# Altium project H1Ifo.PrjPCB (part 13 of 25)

## Sheet IfoSqz1.SchDoc: D1800185
size C; Engineer: Daniel Sigg; DocumentNumber: 4; Revision: 4; SheetNumber: 4; SheetTotal: 10
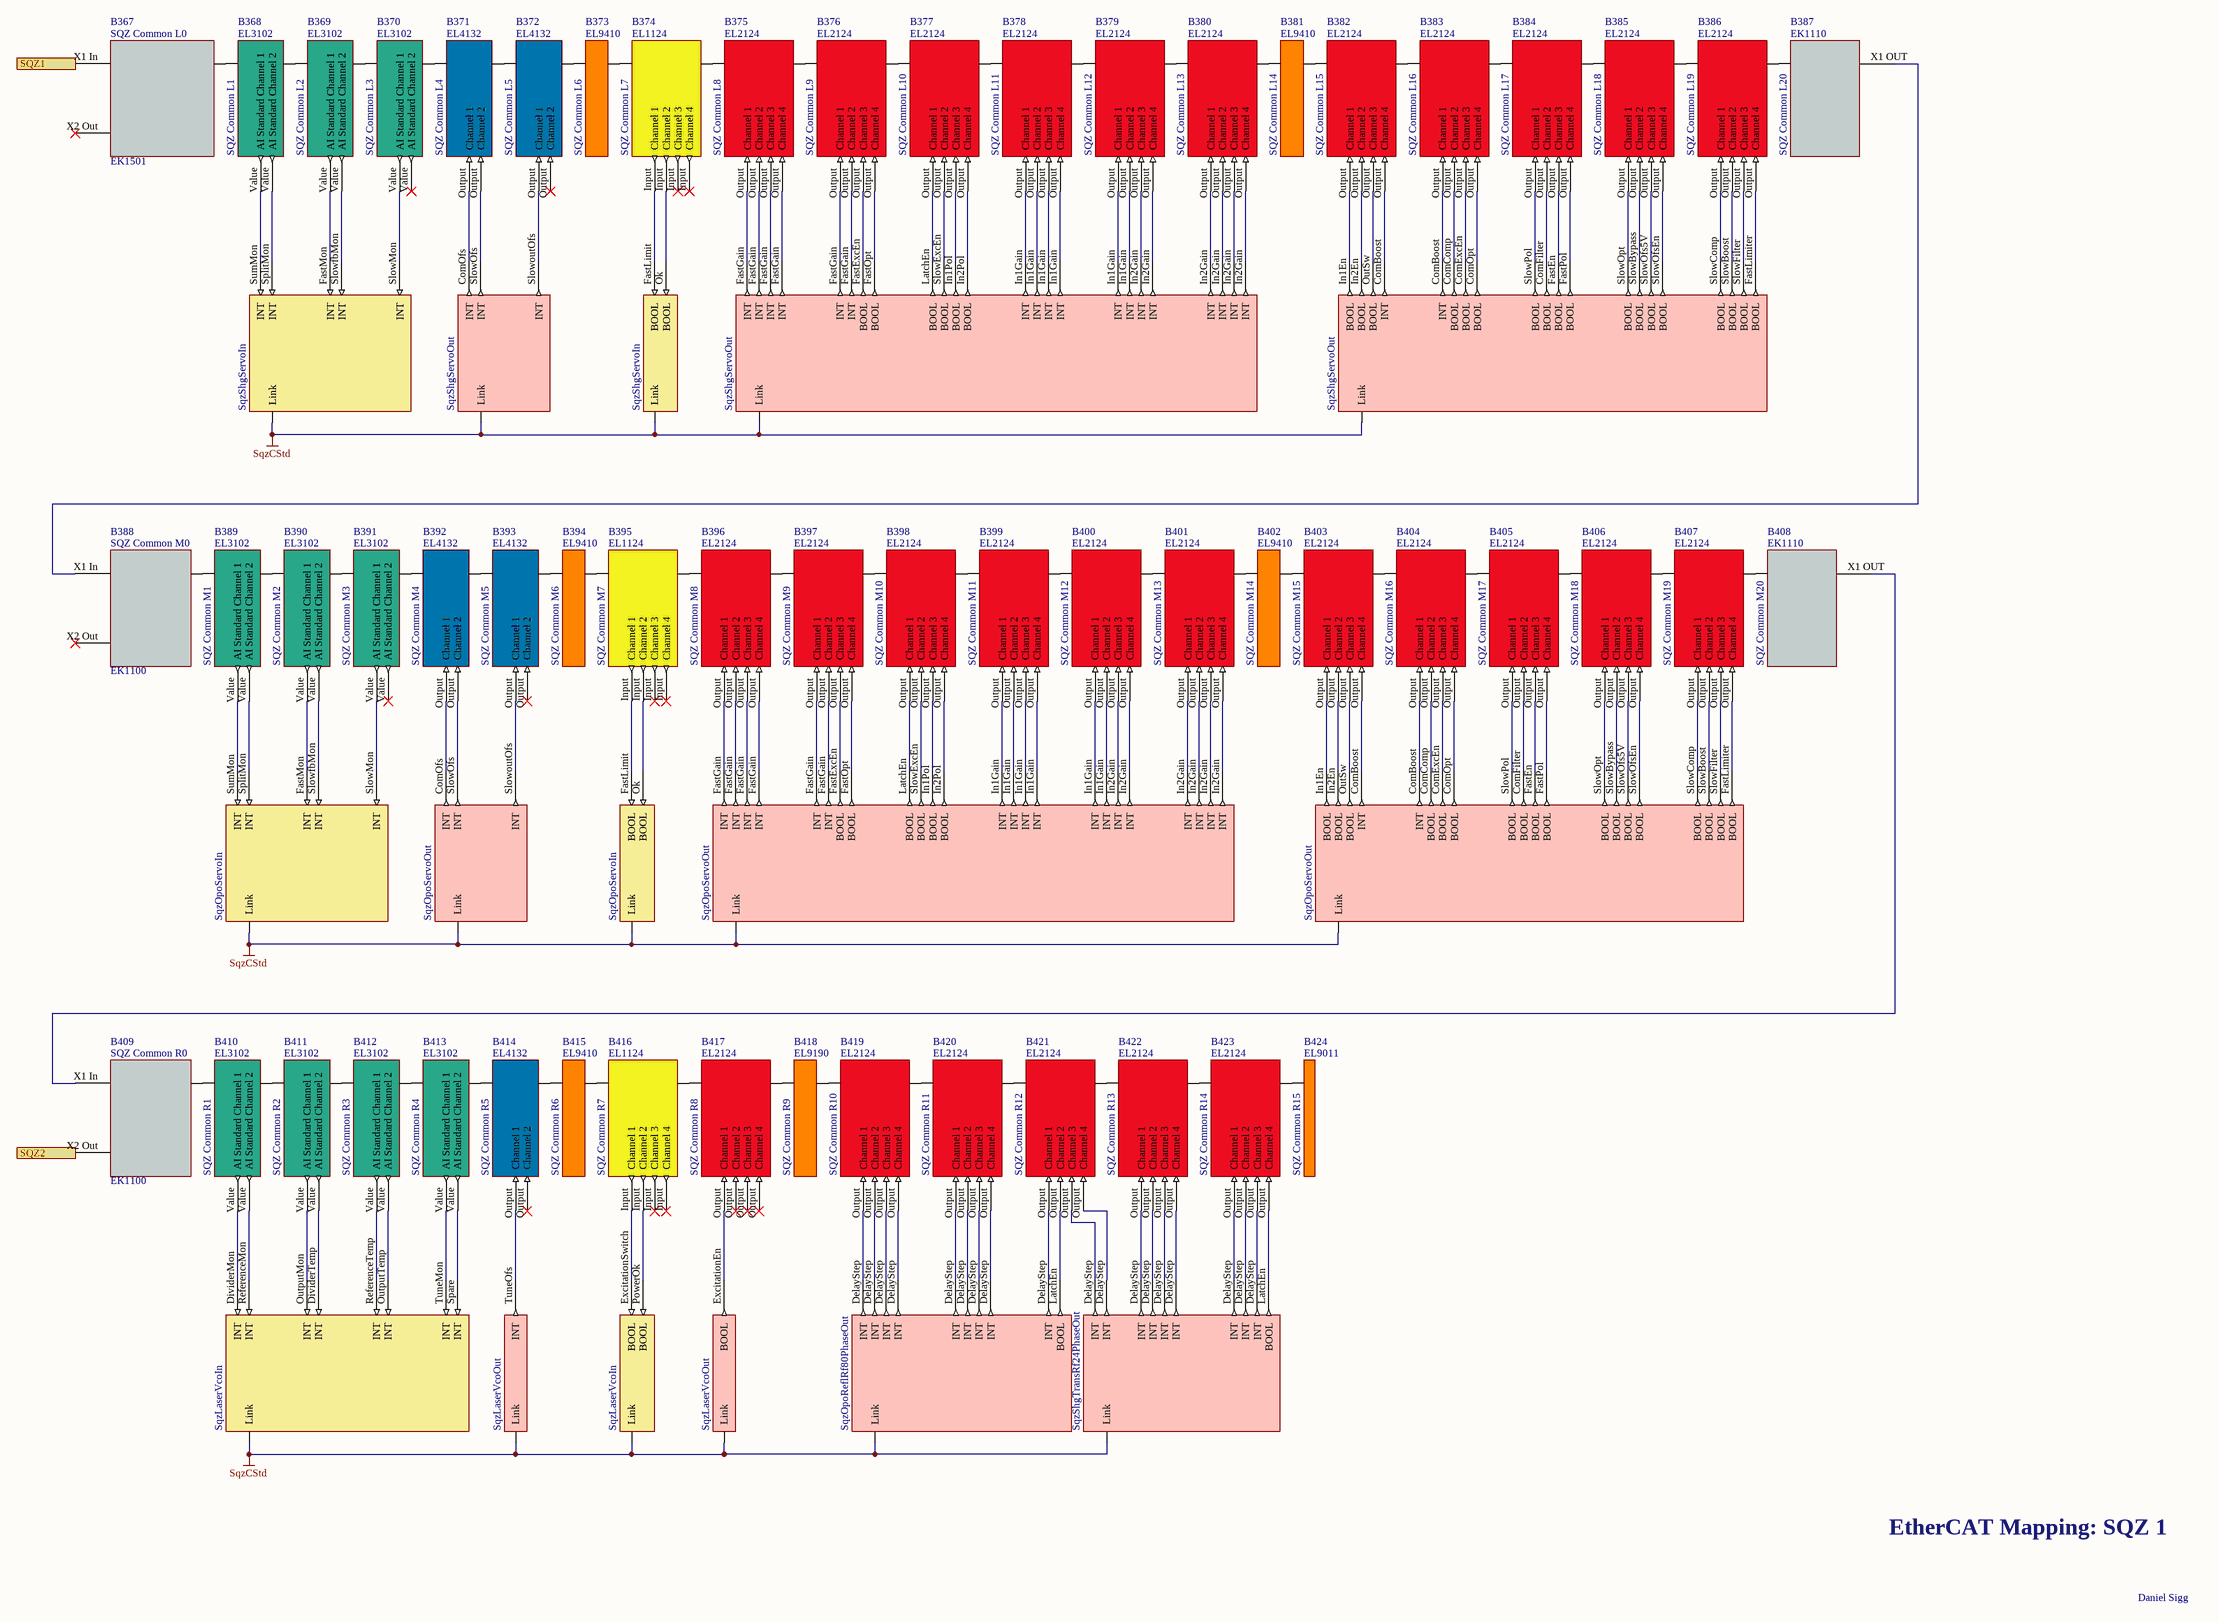
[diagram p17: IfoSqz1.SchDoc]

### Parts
B367  SQZ Common L0  Part Number: EK1501  (mechanical)
B368  SQZ Common L1  Part Number: EL3102  (mechanical)
B369  SQZ Common L2  Part Number: EL3102  (mechanical)
B370  SQZ Common L3  Part Number: EL3102  (mechanical)
B371  SQZ Common L4  Part Number: EL4132  (mechanical)
B372  SQZ Common L5  Part Number: EL4132  (mechanical)
B373  SQZ Common L6  Part Number: EL9410  (mechanical)
B374  SQZ Common L7  Part Number: EL1124  (mechanical)
B375  SQZ Common L8  Part Number: EL2124  (mechanical)
B376  SQZ Common L9  Part Number: EL2124  (mechanical)
B377  SQZ Common L10  Part Number: EL2124  (mechanical)
B378  SQZ Common L11  Part Number: EL2124  (mechanical)
B379  SQZ Common L12  Part Number: EL2124  (mechanical)
B380  SQZ Common L13  Part Number: EL2124  (mechanical)
B381  SQZ Common L14  Part Number: EL9410  (mechanical)
B382  SQZ Common L15  Part Number: EL2124  (mechanical)
B383  SQZ Common L16  Part Number: EL2124  (mechanical)
B384  SQZ Common L17  Part Number: EL2124  (mechanical)
B385  SQZ Common L18  Part Number: EL2124  (mechanical)
B386  SQZ Common L19  Part Number: EL2124  (mechanical)
B387  SQZ Common L20  Part Number: EK1110  (mechanical)
B388  SQZ Common M0  Part Number: EK1100  (mechanical)
B389  SQZ Common M1  Part Number: EL3102  (mechanical)
B390  SQZ Common M2  Part Number: EL3102  (mechanical)
B391  SQZ Common M3  Part Number: EL3102  (mechanical)
B392  SQZ Common M4  Part Number: EL4132  (mechanical)
B393  SQZ Common M5  Part Number: EL4132  (mechanical)
B394  SQZ Common M6  Part Number: EL9410  (mechanical)
B395  SQZ Common M7  Part Number: EL1124  (mechanical)
B396  SQZ Common M8  Part Number: EL2124  (mechanical)
B397  SQZ Common M9  Part Number: EL2124  (mechanical)
B398  SQZ Common M10  Part Number: EL2124  (mechanical)
B399  SQZ Common M11  Part Number: EL2124  (mechanical)
B400  SQZ Common M12  Part Number: EL2124  (mechanical)
B401  SQZ Common M13  Part Number: EL2124  (mechanical)
B402  SQZ Common M14  Part Number: EL9410  (mechanical)
B403  SQZ Common M15  Part Number: EL2124  (mechanical)
B404  SQZ Common M16  Part Number: EL2124  (mechanical)
B405  SQZ Common M17  Part Number: EL2124  (mechanical)
B406  SQZ Common M18  Part Number: EL2124  (mechanical)
B407  SQZ Common M19  Part Number: EL2124  (mechanical)
B408  SQZ Common M20  Part Number: EK1110  (mechanical)
B409  SQZ Common R0  Part Number: EK1100  (mechanical)
B410  SQZ Common R1  Part Number: EL3102  (mechanical)
B411  SQZ Common R2  Part Number: EL3102  (mechanical)
B412  SQZ Common R3  Part Number: EL3102  (mechanical)
B413  SQZ Common R4  Part Number: EL3102  (mechanical)
B414  SQZ Common R5  Part Number: EL4132  (mechanical)
B415  SQZ Common R6  Part Number: EL9410  (mechanical)
B416  SQZ Common R7  Part Number: EL1124  (mechanical)
B417  SQZ Common R8  Part Number: EL2124  (mechanical)
B418  SQZ Common R9  Part Number: EL9190  (mechanical)
B419  SQZ Common R10  Part Number: EL2124  (mechanical)
B420  SQZ Common R11  Part Number: EL2124  (mechanical)
B421  SQZ Common R12  Part Number: EL2124  (mechanical)
B422  SQZ Common R13  Part Number: EL2124  (mechanical)
B423  SQZ Common R14  Part Number: EL2124  (mechanical)
B424  SQZ Common R15  Part Number: EL9011  (mechanical)
V258  SqzShgServoIn  (parts A,B of 2)  (no BOM)
V259  SqzShgServoOut  (parts A,B,C of 3)  (no BOM)
V262  SqzOpoServoIn  (parts A,B of 2)  (no BOM)
V263  SqzOpoServoOut  (parts A,B,C of 3)  (no BOM)
V328  SqzLaserVcoIn  (parts A,B of 2)  (no BOM)
V445  SqzLaserVcoOut  (parts A,B of 2)  (no BOM)
V446  SqzOpoReflRf80PhaseOut  (no BOM)
V447  SqzShgTransRf24PhaseOut  (no BOM)

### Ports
SQZ1, SQZ2

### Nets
SqzCStd: V258.1(Link) V258.?1(Link) V259.1(Link) V259.2(Link) V259.?1(Link) V262.1(Link) V262.?1(Link) V263.1(Link) V263.2(Link) V263.?1(Link) V328.0(Link) V328.1(Link) V445.0(Link) V445.1(Link) V446.?1(Link) V447.?1(Link)
NetB367_Ebus: B367.Ebus(B) B368.Ebus(A)
NetB367_X1 In: B367.X1_In(A) ; port SQZ1
NetB368_Ebus: B368.Ebus(B) B369.Ebus(A)
NetB368_Value: B368.Value(AI_Standard_Channel_1) V258.SumMon(INT)
NetB368_Value: B368.Value(AI_Standard_Channel_2) V258.SplitMon(INT)  [a separate net that carries the same name]
NetB369_Ebus: B369.Ebus(B) B370.Ebus(A)
NetB369_Value: B369.Value(AI_Standard_Channel_1) V258.FastMon(INT)
NetB369_Value: B369.Value(AI_Standard_Channel_2) V258.SlowfbMon(INT)  [a separate net that carries the same name]
NetB370_Ebus: B370.Ebus(B) B371.Ebus(A)
NetB370_Value: B370.Value(AI_Standard_Channel_1) V258.SlowMon(INT)
NetB371_Ebus: B371.Ebus(B) B372.Ebus(A)
NetB371_Output: B371.Output(Channel_1) V259.ComOfs(INT)
NetB371_Output: B371.Output(Channel_2) V259.SlowOfs(INT)  [a separate net that carries the same name]
NetB372_Ebus: B372.Ebus(B) B373.Ebus(A)
NetB372_Output: B372.Output(Channel_1) V259.SlowoutOfs(INT)
NetB373_Ebus: B373.Ebus(B) B374.Ebus(A)
NetB374_Ebus: B374.Ebus(B) B375.Ebus(A)
NetB374_Input: B374.Input(Channel_1) V258.FastLimit(BOOL)
NetB374_Input: B374.Input(Channel_2) V258.Ok(BOOL)  [a separate net that carries the same name]
NetB375_Ebus: B375.Ebus(B) B376.Ebus(A)
NetB375_Output: B375.Output(Channel_1) V259.FastGain(INT)
NetB375_Output: B375.Output(Channel_2) V259.FastGain(INT)  [a separate net that carries the same name]
NetB375_Output: B375.Output(Channel_3) V259.FastGain(INT)  [a separate net that carries the same name]
NetB375_Output: B375.Output(Channel_4) V259.FastGain(INT)  [a separate net that carries the same name]
NetB376_Ebus: B376.Ebus(B) B377.Ebus(A)
NetB376_Output: B376.Output(Channel_1) V259.FastGain(INT)
NetB376_Output: B376.Output(Channel_2) V259.FastGain(INT)  [a separate net that carries the same name]
NetB376_Output: B376.Output(Channel_3) V259.FastExcEn(BOOL)  [a separate net that carries the same name]
NetB376_Output: B376.Output(Channel_4) V259.FastOpt(BOOL)  [a separate net that carries the same name]
NetB377_Ebus: B377.Ebus(B) B378.Ebus(A)
NetB377_Output: B377.Output(Channel_1) V259.LatchEn(BOOL)
NetB377_Output: B377.Output(Channel_2) V259.SlowExcEn(BOOL)  [a separate net that carries the same name]
NetB377_Output: B377.Output(Channel_3) V259.In1Pol(BOOL)  [a separate net that carries the same name]
NetB377_Output: B377.Output(Channel_4) V259.In2Pol(BOOL)  [a separate net that carries the same name]
NetB378_Ebus: B378.Ebus(B) B379.Ebus(A)
NetB378_Output: B378.Output(Channel_1) V259.In1Gain(INT)
NetB378_Output: B378.Output(Channel_2) V259.In1Gain(INT)  [a separate net that carries the same name]
NetB378_Output: B378.Output(Channel_3) V259.In1Gain(INT)  [a separate net that carries the same name]
NetB378_Output: B378.Output(Channel_4) V259.In1Gain(INT)  [a separate net that carries the same name]
NetB379_Ebus: B379.Ebus(B) B380.Ebus(A)
NetB379_Output: B379.Output(Channel_1) V259.In1Gain(INT)
NetB379_Output: B379.Output(Channel_2) V259.In1Gain(INT)  [a separate net that carries the same name]
NetB379_Output: B379.Output(Channel_3) V259.In2Gain(INT)  [a separate net that carries the same name]
NetB379_Output: B379.Output(Channel_4) V259.In2Gain(INT)  [a separate net that carries the same name]
NetB380_Ebus: B380.Ebus(B) B381.Ebus(A)
NetB380_Output: B380.Output(Channel_1) V259.In2Gain(INT)
NetB380_Output: B380.Output(Channel_2) V259.In2Gain(INT)  [a separate net that carries the same name]
NetB380_Output: B380.Output(Channel_3) V259.In2Gain(INT)  [a separate net that carries the same name]
NetB380_Output: B380.Output(Channel_4) V259.In2Gain(INT)  [a separate net that carries the same name]
NetB381_Ebus: B381.Ebus(B) B382.Ebus(A)
NetB382_Ebus: B382.Ebus(B) B383.Ebus(A)
NetB382_Output: B382.Output(Channel_1) V259.In1En(BOOL)
NetB382_Output: B382.Output(Channel_2) V259.In2En(BOOL)  [a separate net that carries the same name]
NetB382_Output: B382.Output(Channel_3) V259.OutSw(BOOL)  [a separate net that carries the same name]
NetB382_Output: B382.Output(Channel_4) V259.ComBoost(INT)  [a separate net that carries the same name]
NetB383_Ebus: B383.Ebus(B) B384.Ebus(A)
NetB383_Output: B383.Output(Channel_1) V259.ComBoost(INT)
NetB383_Output: B383.Output(Channel_2) V259.ComComp(BOOL)  [a separate net that carries the same name]
NetB383_Output: B383.Output(Channel_3) V259.ComExcEn(BOOL)  [a separate net that carries the same name]
NetB383_Output: B383.Output(Channel_4) V259.ComOpt(BOOL)  [a separate net that carries the same name]
NetB384_Ebus: B384.Ebus(B) B385.Ebus(A)
NetB384_Output: B384.Output(Channel_1) V259.SlowPol(BOOL)
NetB384_Output: B384.Output(Channel_2) V259.ComFilter(BOOL)  [a separate net that carries the same name]
NetB384_Output: B384.Output(Channel_3) V259.FastEn(BOOL)  [a separate net that carries the same name]
NetB384_Output: B384.Output(Channel_4) V259.FastPol(BOOL)  [a separate net that carries the same name]
NetB385_Ebus: B385.Ebus(B) B386.Ebus(A)
NetB385_Output: B385.Output(Channel_1) V259.SlowOpt(BOOL)
NetB385_Output: B385.Output(Channel_2) V259.SlowBypass(BOOL)  [a separate net that carries the same name]
NetB385_Output: B385.Output(Channel_3) V259.SlowOfs5V(BOOL)  [a separate net that carries the same name]
NetB385_Output: B385.Output(Channel_4) V259.SlowOfsEn(BOOL)  [a separate net that carries the same name]
NetB386_Ebus: B386.Ebus(B) B387.Ebus(A)
NetB386_Output: B386.Output(Channel_1) V259.SlowComp(BOOL)
NetB386_Output: B386.Output(Channel_2) V259.SlowBoost(BOOL)  [a separate net that carries the same name]
NetB386_Output: B386.Output(Channel_3) V259.SlowFilter(BOOL)  [a separate net that carries the same name]
NetB386_Output: B386.Output(Channel_4) V259.FastLimiter(BOOL)  [a separate net that carries the same name]
NetB387_X1 OUT: B387.X1_OUT(B) B388.X1_In(A)
NetB388_Ebus: B388.Ebus(B) B389.Ebus(A)
NetB389_Ebus: B389.Ebus(B) B390.Ebus(A)
NetB389_Value: B389.Value(AI_Standard_Channel_1) V262.SumMon(INT)
NetB389_Value: B389.Value(AI_Standard_Channel_2) V262.SplitMon(INT)  [a separate net that carries the same name]
NetB390_Ebus: B390.Ebus(B) B391.Ebus(A)
NetB390_Value: B390.Value(AI_Standard_Channel_1) V262.FastMon(INT)
NetB390_Value: B390.Value(AI_Standard_Channel_2) V262.SlowfbMon(INT)  [a separate net that carries the same name]
NetB391_Ebus: B391.Ebus(B) B392.Ebus(A)
NetB391_Value: B391.Value(AI_Standard_Channel_1) V262.SlowMon(INT)
NetB392_Ebus: B392.Ebus(B) B393.Ebus(A)
NetB392_Output: B392.Output(Channel_1) V263.ComOfs(INT)
NetB392_Output: B392.Output(Channel_2) V263.SlowOfs(INT)  [a separate net that carries the same name]
NetB393_Ebus: B393.Ebus(B) B394.Ebus(A)
NetB393_Output: B393.Output(Channel_1) V263.SlowoutOfs(INT)
NetB394_Ebus: B394.Ebus(B) B395.Ebus(A)
NetB395_Ebus: B395.Ebus(B) B396.Ebus(A)
NetB395_Input: B395.Input(Channel_1) V262.FastLimit(BOOL)
NetB395_Input: B395.Input(Channel_2) V262.Ok(BOOL)  [a separate net that carries the same name]
NetB396_Ebus: B396.Ebus(B) B397.Ebus(A)
NetB396_Output: B396.Output(Channel_1) V263.FastGain(INT)
NetB396_Output: B396.Output(Channel_2) V263.FastGain(INT)  [a separate net that carries the same name]
NetB396_Output: B396.Output(Channel_3) V263.FastGain(INT)  [a separate net that carries the same name]
NetB396_Output: B396.Output(Channel_4) V263.FastGain(INT)  [a separate net that carries the same name]
NetB397_Ebus: B397.Ebus(B) B398.Ebus(A)
NetB397_Output: B397.Output(Channel_1) V263.FastGain(INT)
NetB397_Output: B397.Output(Channel_2) V263.FastGain(INT)  [a separate net that carries the same name]
NetB397_Output: B397.Output(Channel_3) V263.FastExcEn(BOOL)  [a separate net that carries the same name]
NetB397_Output: B397.Output(Channel_4) V263.FastOpt(BOOL)  [a separate net that carries the same name]
NetB398_Ebus: B398.Ebus(B) B399.Ebus(A)
NetB398_Output: B398.Output(Channel_1) V263.LatchEn(BOOL)
NetB398_Output: B398.Output(Channel_2) V263.SlowExcEn(BOOL)  [a separate net that carries the same name]
NetB398_Output: B398.Output(Channel_3) V263.In1Pol(BOOL)  [a separate net that carries the same name]
NetB398_Output: B398.Output(Channel_4) V263.In2Pol(BOOL)  [a separate net that carries the same name]
NetB399_Ebus: B399.Ebus(B) B400.Ebus(A)
NetB399_Output: B399.Output(Channel_1) V263.In1Gain(INT)
NetB399_Output: B399.Output(Channel_2) V263.In1Gain(INT)  [a separate net that carries the same name]
NetB399_Output: B399.Output(Channel_3) V263.In1Gain(INT)  [a separate net that carries the same name]
NetB399_Output: B399.Output(Channel_4) V263.In1Gain(INT)  [a separate net that carries the same name]
NetB400_Ebus: B400.Ebus(B) B401.Ebus(A)
NetB400_Output: B400.Output(Channel_1) V263.In1Gain(INT)
NetB400_Output: B400.Output(Channel_2) V263.In1Gain(INT)  [a separate net that carries the same name]
NetB400_Output: B400.Output(Channel_3) V263.In2Gain(INT)  [a separate net that carries the same name]
NetB400_Output: B400.Output(Channel_4) V263.In2Gain(INT)  [a separate net that carries the same name]
NetB401_Ebus: B401.Ebus(B) B402.Ebus(A)
NetB401_Output: B401.Output(Channel_1) V263.In2Gain(INT)
NetB401_Output: B401.Output(Channel_2) V263.In2Gain(INT)  [a separate net that carries the same name]
NetB401_Output: B401.Output(Channel_3) V263.In2Gain(INT)  [a separate net that carries the same name]
NetB401_Output: B401.Output(Channel_4) V263.In2Gain(INT)  [a separate net that carries the same name]
NetB402_Ebus: B402.Ebus(B) B403.Ebus(A)
NetB403_Ebus: B403.Ebus(B) B404.Ebus(A)
NetB403_Output: B403.Output(Channel_1) V263.In1En(BOOL)
NetB403_Output: B403.Output(Channel_2) V263.In2En(BOOL)  [a separate net that carries the same name]
NetB403_Output: B403.Output(Channel_3) V263.OutSw(BOOL)  [a separate net that carries the same name]
NetB403_Output: B403.Output(Channel_4) V263.ComBoost(INT)  [a separate net that carries the same name]
NetB404_Ebus: B404.Ebus(B) B405.Ebus(A)
NetB404_Output: B404.Output(Channel_1) V263.ComBoost(INT)
NetB404_Output: B404.Output(Channel_2) V263.ComComp(BOOL)  [a separate net that carries the same name]
NetB404_Output: B404.Output(Channel_3) V263.ComExcEn(BOOL)  [a separate net that carries the same name]
NetB404_Output: B404.Output(Channel_4) V263.ComOpt(BOOL)  [a separate net that carries the same name]
NetB405_Ebus: B405.Ebus(B) B406.Ebus(A)
NetB405_Output: B405.Output(Channel_1) V263.SlowPol(BOOL)
NetB405_Output: B405.Output(Channel_2) V263.ComFilter(BOOL)  [a separate net that carries the same name]
NetB405_Output: B405.Output(Channel_3) V263.FastEn(BOOL)  [a separate net that carries the same name]
NetB405_Output: B405.Output(Channel_4) V263.FastPol(BOOL)  [a separate net that carries the same name]
NetB406_Ebus: B406.Ebus(B) B407.Ebus(A)
NetB406_Output: B406.Output(Channel_1) V263.SlowOpt(BOOL)
NetB406_Output: B406.Output(Channel_2) V263.SlowBypass(BOOL)  [a separate net that carries the same name]
NetB406_Output: B406.Output(Channel_3) V263.SlowOfs5V(BOOL)  [a separate net that carries the same name]
NetB406_Output: B406.Output(Channel_4) V263.SlowOfsEn(BOOL)  [a separate net that carries the same name]
NetB407_Ebus: B407.Ebus(B) B408.Ebus(A)
NetB407_Output: B407.Output(Channel_1) V263.SlowComp(BOOL)
NetB407_Output: B407.Output(Channel_2) V263.SlowBoost(BOOL)  [a separate net that carries the same name]
NetB407_Output: B407.Output(Channel_3) V263.SlowFilter(BOOL)  [a separate net that carries the same name]
NetB407_Output: B407.Output(Channel_4) V263.FastLimiter(BOOL)  [a separate net that carries the same name]
NetB408_X1 OUT: B408.X1_OUT(B) B409.X1_In(A)
NetB409_Ebus: B409.Ebus(B) B410.Ebus(A)
NetB409_X2 Out: B409.X2_Out(C) ; port SQZ2
NetB410_Ebus: B410.Ebus(B) B411.Ebus(A)
NetB410_Value: B410.Value(AI_Standard_Channel_1) V328.DividerMon(INT)
NetB410_Value: B410.Value(AI_Standard_Channel_2) V328.ReferenceMon(INT)  [a separate net that carries the same name]
NetB411_Ebus: B411.Ebus(B) B412.Ebus(A)
NetB411_Value: B411.Value(AI_Standard_Channel_1) V328.OutputMon(INT)
NetB411_Value: B411.Value(AI_Standard_Channel_2) V328.DividerTemp(INT)  [a separate net that carries the same name]
NetB412_Ebus: B412.Ebus(B) B413.Ebus(A)
NetB412_Value: B412.Value(AI_Standard_Channel_1) V328.ReferenceTemp(INT)
NetB412_Value: B412.Value(AI_Standard_Channel_2) V328.OutputTemp(INT)  [a separate net that carries the same name]
NetB413_Ebus: B413.Ebus(B) B414.Ebus(A)
NetB413_Value: B413.Value(AI_Standard_Channel_1) V328.TuneMon(INT)
NetB413_Value: B413.Value(AI_Standard_Channel_2) V328.Spare(INT)  [a separate net that carries the same name]
NetB414_Ebus: B414.Ebus(B) B415.Ebus(A)
NetB414_Output: B414.Output(Channel_1) V445.TuneOfs(INT)
NetB415_Ebus: B415.Ebus(B) B416.Ebus(A)
NetB416_Ebus: B416.Ebus(B) B417.Ebus(A)
NetB416_Input: B416.Input(Channel_1) V328.ExcitationSwitch(BOOL)
NetB416_Input: B416.Input(Channel_2) V328.PowerOk(BOOL)  [a separate net that carries the same name]
NetB417_Ebus: B417.Ebus(B) B418.Ebus(A)
NetB417_Output: B417.Output(Channel_1) V445.ExcitationEn(BOOL)
NetB418_Ebus: B418.Ebus(B) B419.Ebus(A)
NetB419_Ebus: B419.Ebus(B) B420.Ebus(A)
NetB419_Output: B419.Output(Channel_1) V446.DelayStep(INT)
NetB419_Output: B419.Output(Channel_2) V446.DelayStep(INT)  [a separate net that carries the same name]
NetB419_Output: B419.Output(Channel_3) V446.DelayStep(INT)  [a separate net that carries the same name]
NetB419_Output: B419.Output(Channel_4) V446.DelayStep(INT)  [a separate net that carries the same name]
NetB420_Ebus: B420.Ebus(B) B421.Ebus(A)
NetB420_Output: B420.Output(Channel_1) V446.DelayStep(INT)
NetB420_Output: B420.Output(Channel_2) V446.DelayStep(INT)  [a separate net that carries the same name]
NetB420_Output: B420.Output(Channel_3) V446.DelayStep(INT)  [a separate net that carries the same name]
NetB420_Output: B420.Output(Channel_4) V446.DelayStep(INT)  [a separate net that carries the same name]
NetB421_Ebus: B421.Ebus(B) B422.Ebus(A)
NetB421_Output: B421.Output(Channel_1) V446.DelayStep(INT)
NetB421_Output: B421.Output(Channel_2) V446.LatchEn(BOOL)  [a separate net that carries the same name]
NetB421_Output: B421.Output(Channel_3) V447.DelayStep(INT)  [a separate net that carries the same name]
NetB421_Output: B421.Output(Channel_4) V447.DelayStep(INT)  [a separate net that carries the same name]
NetB422_Ebus: B422.Ebus(B) B423.Ebus(A)
NetB422_Output: B422.Output(Channel_1) V447.DelayStep(INT)
NetB422_Output: B422.Output(Channel_2) V447.DelayStep(INT)  [a separate net that carries the same name]
NetB422_Output: B422.Output(Channel_3) V447.DelayStep(INT)  [a separate net that carries the same name]
NetB422_Output: B422.Output(Channel_4) V447.DelayStep(INT)  [a separate net that carries the same name]
NetB423_Ebus: B423.Ebus(B) B424.Ebus(A)
NetB423_Output: B423.Output(Channel_1) V447.DelayStep(INT)
NetB423_Output: B423.Output(Channel_2) V447.DelayStep(INT)  [a separate net that carries the same name]
NetB423_Output: B423.Output(Channel_3) V447.DelayStep(INT)  [a separate net that carries the same name]
NetB423_Output: B423.Output(Channel_4) V447.LatchEn(BOOL)  [a separate net that carries the same name]

Not connected (* = marked no-connect by the designer): B367 X2 Out(C)*; B388 X2 Out(C)*

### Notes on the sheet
- EtherCAT Mapping: SQZ 1
- Daniel Sigg

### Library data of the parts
B367 = CouplerEK1501: Fiber Coupler; Rail: Left; BoxNextB: VSNCGPIA; BoxPrev: BXBUSGVQ; PortPrevFull: 1001/B; PortPrevShort: B 'X1'; Fullname: TIID^Vertex Squeezer (EtherCAT)^SQZ Common L0 (EK1501); BoxPorts: Junction; BoxAddr: 1002; Disabled: False
B368 = TerminalEL3102: EtherCAT Terminal EL3102 2-chn Analog Input; Rail: Left; BoxNextB: YCFLFBLV; BoxPrev: STIDPCUW; PortPrevFull: 1002/B; PortPrevShort: B; Fullname: TIID^Vertex Squeezer (EtherCAT)^SQZ Common L0 (EK1501)^SQZ Common L1 (EL3102); BoxAddr: 1003; Disabled: False
B369 = TerminalEL3102: EtherCAT Terminal EL3102 2-chn Analog Input; Rail: Left; BoxNextB: QULDFKFG; BoxPrev: VSNCGPIA; PortPrevFull: 1003/B; PortPrevShort: B; Fullname: TIID^Vertex Squeezer (EtherCAT)^SQZ Common L0 (EK1501)^SQZ Common L2 (EL3102); BoxAddr: 1004; Disabled: False
B370 = TerminalEL3102: EtherCAT Terminal EL3102 2-chn Analog Input; Rail: Left; BoxNextB: OEGSMRUH; BoxPrev: YCFLFBLV; PortPrevFull: 1004/B; PortPrevShort: B; Fullname: TIID^Vertex Squeezer (EtherCAT)^SQZ Common L0 (EK1501)^SQZ Common L3 (EL3102); BoxAddr: 1005; Disabled: False
B371 = TerminalEL4132: EtherCAT Terminal EL4132 2-chn Analog Ouput; Rail: Left; BoxNextB: GSJQHMUK; BoxPrev: QULDFKFG; PortPrevFull: 1005/B; PortPrevShort: B; Fullname: TIID^Vertex Squeezer (EtherCAT)^SQZ Common L0 (EK1501)^SQZ Common L4 (EL4132); BoxAddr: 1006; Disabled: False
B372 = TerminalEL4132: EtherCAT Terminal EL4132 2-chn Analog Ouput; Rail: Left; BoxNextB: RSDFWBCD; BoxPrev: OEGSMRUH; PortPrevFull: 1006/B; PortPrevShort: B; Fullname: TIID^Vertex Squeezer (EtherCAT)^SQZ Common L0 (EK1501)^SQZ Common L5 (EL4132); BoxAddr: 1007; Disabled: False
B373 = TerminalEL9410: EtherCAT Terminal EL9410 Power; Rail: Left; BoxNextB: IPIGFJCX; BoxPrev: GSJQHMUK; PortPrevFull: 1007/B; PortPrevShort: B; Fullname: TIID^Vertex Squeezer (EtherCAT)^SQZ Common L0 (EK1501)^SQZ Common L6 (EL9410); BoxAddr: 1008; Disabled: False
B374 = TerminalEL1124: EtherCAT Terminal EL1124 4-chn Digital Input; Rail: Left; BoxNextB: VCFVXCDL; BoxPrev: RSDFWBCD; PortPrevFull: 1008/B; PortPrevShort: B; Fullname: TIID^Vertex Squeezer (EtherCAT)^SQZ Common L0 (EK1501)^SQZ Common L7 (EL1124); BoxAddr: 1009; Disabled: False
B375 = TerminalEL2124: EtherCAT Terminal EL2124 4-chn Digital Ouput; Rail: Left; BoxNextB: HGMOIBSD; BoxPrev: IPIGFJCX; PortPrevFull: 1009/B; PortPrevShort: B; Fullname: TIID^Vertex Squeezer (EtherCAT)^SQZ Common L0 (EK1501)^SQZ Common L8 (EL2124); BoxAddr: 1010; Disabled: False
B376 = TerminalEL2124: EtherCAT Terminal EL2124 4-chn Digital Ouput; Rail: Left; BoxNextB: RINVLXUB; BoxPrev: VCFVXCDL; PortPrevFull: 1010/B; PortPrevShort: B; Fullname: TIID^Vertex Squeezer (EtherCAT)^SQZ Common L0 (EK1501)^SQZ Common L9 (EL2124); BoxAddr: 1011; Disabled: False
B377 = TerminalEL2124: EtherCAT Terminal EL2124 4-chn Digital Ouput; Rail: Left; BoxNextB: QHGUEJGC; BoxPrev: HGMOIBSD; PortPrevFull: 1011/B; PortPrevShort: B; Fullname: TIID^Vertex Squeezer (EtherCAT)^SQZ Common L0 (EK1501)^SQZ Common L10 (EL2124); BoxAddr: 1012; Disabled: False
B378 = TerminalEL2124: EtherCAT Terminal EL2124 4-chn Digital Ouput; Rail: Left; BoxNextB: BJSIHCKK; BoxPrev: RINVLXUB; PortPrevFull: 1012/B; PortPrevShort: B; Fullname: TIID^Vertex Squeezer (EtherCAT)^SQZ Common L0 (EK1501)^SQZ Common L11 (EL2124); BoxAddr: 1013; Disabled: False
B379 = TerminalEL2124: EtherCAT Terminal EL2124 4-chn Digital Ouput; Rail: Left; BoxNextB: OHBMVYSG; BoxPrev: QHGUEJGC; PortPrevFull: 1013/B; PortPrevShort: B; Fullname: TIID^Vertex Squeezer (EtherCAT)^SQZ Common L0 (EK1501)^SQZ Common L12 (EL2124); BoxAddr: 1014; Disabled: False
B380 = TerminalEL2124: EtherCAT Terminal EL2124 4-chn Digital Ouput; Rail: Left; BoxNextB: RIYFMODB; BoxPrev: BJSIHCKK; PortPrevFull: 1014/B; PortPrevShort: B; Fullname: TIID^Vertex Squeezer (EtherCAT)^SQZ Common L0 (EK1501)^SQZ Common L13 (EL2124); BoxAddr: 1015; Disabled: False
B381 = TerminalEL9410: EtherCAT Terminal EL9410 Power; Rail: Left; BoxNextB: GDFFOSXA; BoxPrev: OHBMVYSG; PortPrevFull: 1015/B; PortPrevShort: B; Fullname: TIID^Vertex Squeezer (EtherCAT)^SQZ Common L0 (EK1501)^SQZ Common L14 (EL9410); BoxAddr: 1016; Disabled: False
B382 = TerminalEL2124: EtherCAT Terminal EL2124 4-chn Digital Ouput; Rail: Left; BoxNextB: PNXOWBON; BoxPrev: RIYFMODB; PortPrevFull: 1016/B; PortPrevShort: B; Fullname: TIID^Vertex Squeezer (EtherCAT)^SQZ Common L0 (EK1501)^SQZ Common L15 (EL2124); BoxAddr: 1017; Disabled: False
B383 = TerminalEL2124: EtherCAT Terminal EL2124 4-chn Digital Ouput; Rail: Left; BoxNextB: JYEDWUFP; BoxPrev: GDFFOSXA; PortPrevFull: 1017/B; PortPrevShort: B; Fullname: TIID^Vertex Squeezer (EtherCAT)^SQZ Common L0 (EK1501)^SQZ Common L16 (EL2124); BoxAddr: 1018; Disabled: False
B384 = TerminalEL2124: EtherCAT Terminal EL2124 4-chn Digital Ouput; Rail: Left; BoxNextB: NVPRLEVX; BoxPrev: PNXOWBON; PortPrevFull: 1018/B; PortPrevShort: B; Fullname: TIID^Vertex Squeezer (EtherCAT)^SQZ Common L0 (EK1501)^SQZ Common L17 (EL2124); BoxAddr: 1019; Disabled: False
B385 = TerminalEL2124: EtherCAT Terminal EL2124 4-chn Digital Ouput; Rail: Left; BoxNextB: MPCXIVGR; BoxPrev: JYEDWUFP; PortPrevFull: 1019/B; PortPrevShort: B; Fullname: TIID^Vertex Squeezer (EtherCAT)^SQZ Common L0 (EK1501)^SQZ Common L18 (EL2124); BoxAddr: 1020; Disabled: False
B386 = TerminalEL2124: EtherCAT Terminal EL2124 4-chn Digital Ouput; Rail: Left; BoxNextB: HUKLVRRO; BoxPrev: NVPRLEVX; PortPrevFull: 1020/B; PortPrevShort: B; Fullname: TIID^Vertex Squeezer (EtherCAT)^SQZ Common L0 (EK1501)^SQZ Common L19 (EL2124); BoxAddr: 1021; Disabled: False
B387 = CouplerEK1110: EtherCAT Coupler Extension; BoxType: Terminal; Rail: Left; BoxNextB: CAPUFQDF; BoxPrev: MPCXIVGR; PortPrevFull: 1021/B; PortPrevShort: B; Fullname: TIID^Vertex Squeezer (EtherCAT)^SQZ Common L0 (EK1501)^SQZ Common L20 (EK1110); BoxAddr: 1022; Disabled: False
B388 = CouplerEK1100: EtherCAT Coupler; Rail: Middle; BoxNextB: OQBHSEIY; BoxPrev: HUKLVRRO; PortPrevFull: 1022/B; PortPrevShort: B 'X1 OUT'; Fullname: TIID^Vertex Squeezer (EtherCAT)^SQZ Common M0 (EK1100); BoxPorts: Junction; BoxAddr: 1023; Disabled: False
B389 = TerminalEL3102: EtherCAT Terminal EL3102 2-chn Analog Input; Rail: Middle; BoxNextB: GTBHSNBT; BoxPrev: CAPUFQDF; PortPrevFull: 1023/B; PortPrevShort: B; Fullname: TIID^Vertex Squeezer (EtherCAT)^SQZ Common M0 (EK1100)^SQZ Common M1 (EL3102); BoxAddr: 1024; Disabled: False
B390 = TerminalEL3102: EtherCAT Terminal EL3102 2-chn Analog Input; Rail: Middle; BoxNextB: INVPRYXB; BoxPrev: OQBHSEIY; PortPrevFull: 1024/B; PortPrevShort: B; Fullname: TIID^Vertex Squeezer (EtherCAT)^SQZ Common M0 (EK1100)^SQZ Common M2 (EL3102); BoxAddr: 1025; Disabled: False
B391 = TerminalEL3102: EtherCAT Terminal EL3102 2-chn Analog Input; Rail: Middle; BoxNextB: VEJPHFHM; BoxPrev: GTBHSNBT; PortPrevFull: 1025/B; PortPrevShort: B; Fullname: TIID^Vertex Squeezer (EtherCAT)^SQZ Common M0 (EK1100)^SQZ Common M3 (EL3102); BoxAddr: 1026; Disabled: False
B392 = TerminalEL4132: EtherCAT Terminal EL4132 2-chn Analog Ouput; Rail: Middle; BoxNextB: SWXUCNAX; BoxPrev: INVPRYXB; PortPrevFull: 1026/B; PortPrevShort: B; Fullname: TIID^Vertex Squeezer (EtherCAT)^SQZ Common M0 (EK1100)^SQZ Common M4 (EL4132); BoxAddr: 1027; Disabled: False
B393 = TerminalEL4132: EtherCAT Terminal EL4132 2-chn Analog Ouput; Rail: Middle; BoxNextB: XQKPPVAB; BoxPrev: VEJPHFHM; PortPrevFull: 1027/B; PortPrevShort: B; Fullname: TIID^Vertex Squeezer (EtherCAT)^SQZ Common M0 (EK1100)^SQZ Common M5 (EL4132); BoxAddr: 1028; Disabled: False
B394 = TerminalEL9410: EtherCAT Terminal EL9410 Power; Rail: Middle; BoxNextB: KSKWJIPU; BoxPrev: SWXUCNAX; PortPrevFull: 1028/B; PortPrevShort: B; Fullname: TIID^Vertex Squeezer (EtherCAT)^SQZ Common M0 (EK1100)^SQZ Common M6 (EL9410); BoxAddr: 1029; Disabled: False
B395 = TerminalEL1124: EtherCAT Terminal EL1124 4-chn Digital Input; Rail: Middle; BoxNextB: GGJCEIBS; BoxPrev: XQKPPVAB; PortPrevFull: 1029/B; PortPrevShort: B; Fullname: TIID^Vertex Squeezer (EtherCAT)^SQZ Common M0 (EK1100)^SQZ Common M7 (EL1124); BoxAddr: 1030; Disabled: False
B396 = TerminalEL2124: EtherCAT Terminal EL2124 4-chn Digital Ouput; Rail: Middle; BoxNextB: AMYQDIAT; BoxPrev: KSKWJIPU; PortPrevFull: 1030/B; PortPrevShort: B; Fullname: TIID^Vertex Squeezer (EtherCAT)^SQZ Common M0 (EK1100)^SQZ Common M8 (EL2124); BoxAddr: 1031; Disabled: False
B397 = TerminalEL2124: EtherCAT Terminal EL2124 4-chn Digital Ouput; Rail: Middle; BoxNextB: VSKVFRHN; BoxPrev: GGJCEIBS; PortPrevFull: 1031/B; PortPrevShort: B; Fullname: TIID^Vertex Squeezer (EtherCAT)^SQZ Common M0 (EK1100)^SQZ Common M9 (EL2124); BoxAddr: 1032; Disabled: False
B398 = TerminalEL2124: EtherCAT Terminal EL2124 4-chn Digital Ouput; Rail: Middle; BoxNextB: WITMKDOM; BoxPrev: AMYQDIAT; PortPrevFull: 1032/B; PortPrevShort: B; Fullname: TIID^Vertex Squeezer (EtherCAT)^SQZ Common M0 (EK1100)^SQZ Common M10 (EL2124); BoxAddr: 1033; Disabled: False
B399 = TerminalEL2124: EtherCAT Terminal EL2124 4-chn Digital Ouput; Rail: Middle; BoxNextB: PLQPHDWW; BoxPrev: VSKVFRHN; PortPrevFull: 1033/B; PortPrevShort: B; Fullname: TIID^Vertex Squeezer (EtherCAT)^SQZ Common M0 (EK1100)^SQZ Common M11 (EL2124); BoxAddr: 1034; Disabled: False
B400 = TerminalEL2124: EtherCAT Terminal EL2124 4-chn Digital Ouput; Rail: Middle; BoxNextB: GJLVIBSU; BoxPrev: WITMKDOM; PortPrevFull: 1034/B; PortPrevShort: B; Fullname: TIID^Vertex Squeezer (EtherCAT)^SQZ Common M0 (EK1100)^SQZ Common M12 (EL2124); BoxAddr: 1035; Disabled: False
B401 = TerminalEL2124: EtherCAT Terminal EL2124 4-chn Digital Ouput; Rail: Middle; BoxNextB: MYDQPFUI; BoxPrev: PLQPHDWW; PortPrevFull: 1035/B; PortPrevShort: B; Fullname: TIID^Vertex Squeezer (EtherCAT)^SQZ Common M0 (EK1100)^SQZ Common M13 (EL2124); BoxAddr: 1036; Disabled: False
B402 = TerminalEL9410: EtherCAT Terminal EL9410 Power; Rail: Middle; BoxNextB: TSXFHNXM; BoxPrev: GJLVIBSU; PortPrevFull: 1036/B; PortPrevShort: B; Fullname: TIID^Vertex Squeezer (EtherCAT)^SQZ Common M0 (EK1100)^SQZ Common M14 (EL9410); BoxAddr: 1037; Disabled: False
B403 = TerminalEL2124: EtherCAT Terminal EL2124 4-chn Digital Ouput; Rail: Middle; BoxNextB: DUULLEBB; BoxPrev: MYDQPFUI; PortPrevFull: 1037/B; PortPrevShort: B; Fullname: TIID^Vertex Squeezer (EtherCAT)^SQZ Common M0 (EK1100)^SQZ Common M15 (EL2124); BoxAddr: 1038; Disabled: False
B404 = TerminalEL2124: EtherCAT Terminal EL2124 4-chn Digital Ouput; Rail: Middle; BoxNextB: XTONPBLY; BoxPrev: TSXFHNXM; PortPrevFull: 1038/B; PortPrevShort: B; Fullname: TIID^Vertex Squeezer (EtherCAT)^SQZ Common M0 (EK1100)^SQZ Common M16 (EL2124); BoxAddr: 1039; Disabled: False
B405 = TerminalEL2124: EtherCAT Terminal EL2124 4-chn Digital Ouput; Rail: Middle; BoxNextB: IBJJRYOV; BoxPrev: DUULLEBB; PortPrevFull: 1039/B; PortPrevShort: B; Fullname: TIID^Vertex Squeezer (EtherCAT)^SQZ Common M0 (EK1100)^SQZ Common M17 (EL2124); BoxAddr: 1040; Disabled: False
B406 = TerminalEL2124: EtherCAT Terminal EL2124 4-chn Digital Ouput; Rail: Middle; BoxNextB: MJVAUPNY; BoxPrev: XTONPBLY; PortPrevFull: 1040/B; PortPrevShort: B; Fullname: TIID^Vertex Squeezer (EtherCAT)^SQZ Common M0 (EK1100)^SQZ Common M18 (EL2124); BoxAddr: 1041; Disabled: False
B407 = TerminalEL2124: EtherCAT Terminal EL2124 4-chn Digital Ouput; Rail: Middle; BoxNextB: GCDLFMCO; BoxPrev: IBJJRYOV; PortPrevFull: 1041/B; PortPrevShort: B; Fullname: TIID^Vertex Squeezer (EtherCAT)^SQZ Common M0 (EK1100)^SQZ Common M19 (EL2124); BoxAddr: 1042; Disabled: False
B408 = CouplerEK1110: EtherCAT Coupler Extension; BoxType: Terminal; Rail: Middle; BoxNextB: CHFWIWBW; BoxPrev: MJVAUPNY; PortPrevFull: 1042/B; PortPrevShort: B; Fullname: TIID^Vertex Squeezer (EtherCAT)^SQZ Common M0 (EK1100)^SQZ Common M20 (EK1110); BoxAddr: 1043; Disabled: False
B409 = CouplerEK1100: EtherCAT Coupler; Rail: Right; BoxNextB: HBPTGKAB; BoxNextC: HHKDCWNA; BoxPrev: GCDLFMCO; PortPrevFull: 1043/B; PortPrevShort: B 'X1 OUT'; Fullname: TIID^Vertex Squeezer (EtherCAT)^SQZ Common R0 (EK1100); BoxPorts: Junction; BoxAddr: 1044; Disabled: False
B410 = TerminalEL3102: EtherCAT Terminal EL3102 2-chn Analog Input; Rail: Right; BoxNextB: LTHAEORB; BoxPrev: CHFWIWBW; PortPrevFull: 1044/B; PortPrevShort: B; Fullname: TIID^Vertex Squeezer (EtherCAT)^SQZ Common R0 (EK1100)^SQZ Common R1 (EL3102); BoxAddr: 1045; Disabled: False
B411 = TerminalEL3102: EtherCAT Terminal EL3102 2-chn Analog Input; Rail: Right; BoxNextB: MSVAWCOE; BoxPrev: HBPTGKAB; PortPrevFull: 1045/B; PortPrevShort: B; Fullname: TIID^Vertex Squeezer (EtherCAT)^SQZ Common R0 (EK1100)^SQZ Common R2 (EL3102); BoxAddr: 1046; Disabled: False
B412 = TerminalEL3102: EtherCAT Terminal EL3102 2-chn Analog Input; Rail: Right; BoxNextB: QULSFNVM; BoxPrev: LTHAEORB; PortPrevFull: 1046/B; PortPrevShort: B; Fullname: TIID^Vertex Squeezer (EtherCAT)^SQZ Common R0 (EK1100)^SQZ Common R3 (EL3102); BoxAddr: 1047; Disabled: False
B413 = TerminalEL3102: EtherCAT Terminal EL3102 2-chn Analog Input; Rail: Right; BoxNextB: XPFQEYUL; BoxPrev: MSVAWCOE; PortPrevFull: 1047/B; PortPrevShort: B; Fullname: TIID^Vertex Squeezer (EtherCAT)^SQZ Common R0 (EK1100)^SQZ Common R4 (EL3102); BoxAddr: 1048; Disabled: False
B414 = TerminalEL4132: EtherCAT Terminal EL4132 2-chn Analog Ouput; Rail: Right; BoxNextB: JALFRJXO; BoxPrev: QULSFNVM; PortPrevFull: 1048/B; PortPrevShort: B; Fullname: TIID^Vertex Squeezer (EtherCAT)^SQZ Common R0 (EK1100)^SQZ Common R5 (EL4132); BoxAddr: 1049; Disabled: False
B415 = TerminalEL9410: EtherCAT Terminal EL9410 Power; Rail: Right; BoxNextB: NQOLQQHK; BoxPrev: XPFQEYUL; PortPrevFull: 1049/B; PortPrevShort: B; Fullname: TIID^Vertex Squeezer (EtherCAT)^SQZ Common R0 (EK1100)^SQZ Common R6 (EL9410); BoxAddr: 1050; Disabled: False
B416 = TerminalEL1124: EtherCAT Terminal EL1124 4-chn Digital Input; Rail: Right; BoxNextB: XJIVYRVD; BoxPrev: JALFRJXO; PortPrevFull: 1050/B; PortPrevShort: B; Fullname: TIID^Vertex Squeezer (EtherCAT)^SQZ Common R0 (EK1100)^SQZ Common R7 (EL1124); BoxAddr: 1051; Disabled: False
B417 = TerminalEL2124: EtherCAT Terminal EL2124 4-chn Digital Ouput; Rail: Right; BoxNextB: WHRQRFBY; BoxPrev: NQOLQQHK; PortPrevFull: 1051/B; PortPrevShort: B; Fullname: TIID^Vertex Squeezer (EtherCAT)^SQZ Common R0 (EK1100)^SQZ Common R8 (EL2124); BoxAddr: 1052; Disabled: False
B418 = TerminalEL9190: EtherCAT Terminal EL9190 Supply; BoxType: TerminalPassive; Rail: Right; BoxNextB: VQLPBFBK; BoxPrev: XJIVYRVD; PortPrevShort: B; Fullname: TIID^Vertex Squeezer (EtherCAT)^SQZ Common R0 (EK1100)^SQZ Common R9 (EL9190); Disabled: False
B419 = TerminalEL2124: EtherCAT Terminal EL2124 4-chn Digital Ouput; Rail: Right; BoxNextB: FTCNALOG; BoxPrev: WHRQRFBY; PortPrevFull: 1052/B; PortPrevShort: B; Fullname: TIID^Vertex Squeezer (EtherCAT)^SQZ Common R0 (EK1100)^SQZ Common R10 (EL2124); BoxAddr: 1053; Disabled: False
B420 = TerminalEL2124: EtherCAT Terminal EL2124 4-chn Digital Ouput; Rail: Right; BoxNextB: CLOXBUGM; BoxPrev: VQLPBFBK; PortPrevFull: 1053/B; PortPrevShort: B; Fullname: TIID^Vertex Squeezer (EtherCAT)^SQZ Common R0 (EK1100)^SQZ Common R11 (EL2124); BoxAddr: 1054; Disabled: False
B421 = TerminalEL2124: EtherCAT Terminal EL2124 4-chn Digital Ouput; Rail: Right; BoxNextB: HIDCDBRC; BoxPrev: FTCNALOG; PortPrevFull: 1054/B; PortPrevShort: B; Fullname: TIID^Vertex Squeezer (EtherCAT)^SQZ Common R0 (EK1100)^SQZ Common R12 (EL2124); BoxAddr: 1055; Disabled: False
B422 = TerminalEL2124: EtherCAT Terminal EL2124 4-chn Digital Ouput; Rail: Right; BoxNextB: TININXQF; BoxPrev: CLOXBUGM; PortPrevFull: 1055/B; PortPrevShort: B; Fullname: TIID^Vertex Squeezer (EtherCAT)^SQZ Common R0 (EK1100)^SQZ Common R13 (EL2124); BoxAddr: 1056; Disabled: False
B423 = TerminalEL2124: EtherCAT Terminal EL2124 4-chn Digital Ouput; Rail: Right; BoxNextB: FITUTSMW; BoxPrev: HIDCDBRC; PortPrevFull: 1056/B; PortPrevShort: B; Fullname: TIID^Vertex Squeezer (EtherCAT)^SQZ Common R0 (EK1100)^SQZ Common R14 (EL2124); BoxAddr: 1057; Disabled: False
B424 = TerminalEL9011: EtherCAT Terminal EL9011 End; BoxType: TerminalPassive; Rail: Right; BoxPrev: TININXQF; PortPrevShort: B; Fullname: TIID^Vertex Squeezer (EtherCAT)^SQZ Common R0 (EK1100)^SQZ Common R15 (EL9011); Disabled: False
V258 V262 = CommonMode_CommonModeInStruct: CommonModeInStruct; BoxType: Variable; Instance: H1SqzCorner Instance; PLC: H1SqzCorner; Task: SqzCStd
V259 V263 = CommonMode_CommonModeOutStruct: CommonModeOutStruct; BoxType: Variable; Instance: H1SqzCorner Instance; PLC: H1SqzCorner; Task: SqzCStd
V328 = LowNoiseVco_LowNoiseVcoInStruct: LowNoiseVcoInStruct; BoxType: Variable; Instance: H1SqzCorner Instance; PLC: H1SqzCorner; Task: SqzCStd
V445 = LowNoiseVco_LowNoiseVcoOutStruct: LowNoiseVcoOutStruct; BoxType: Variable; Instance: H1SqzCorner Instance; PLC: H1SqzCorner; Task: SqzCStd
V446 = DelayLogic_DelayLogicOutStruct: DelayLogicOutStruct; BoxType: Variable; Instance: H1SqzCorner Instance; PLC: H1SqzCorner; Task: SqzCStd
V447 = DelayLogic_DelayLogicOutStructB: DelayLogicOutStruct; BoxType: Variable; Instance: H1SqzCorner Instance; PLC: H1SqzCorner; Task: SqzCStd

## Sheet IfoSqz2.SchDoc: D1800185
size C; Engineer: Daniel Sigg; DocumentNumber: 5; Revision: 4; SheetNumber: 5; SheetTotal: 10
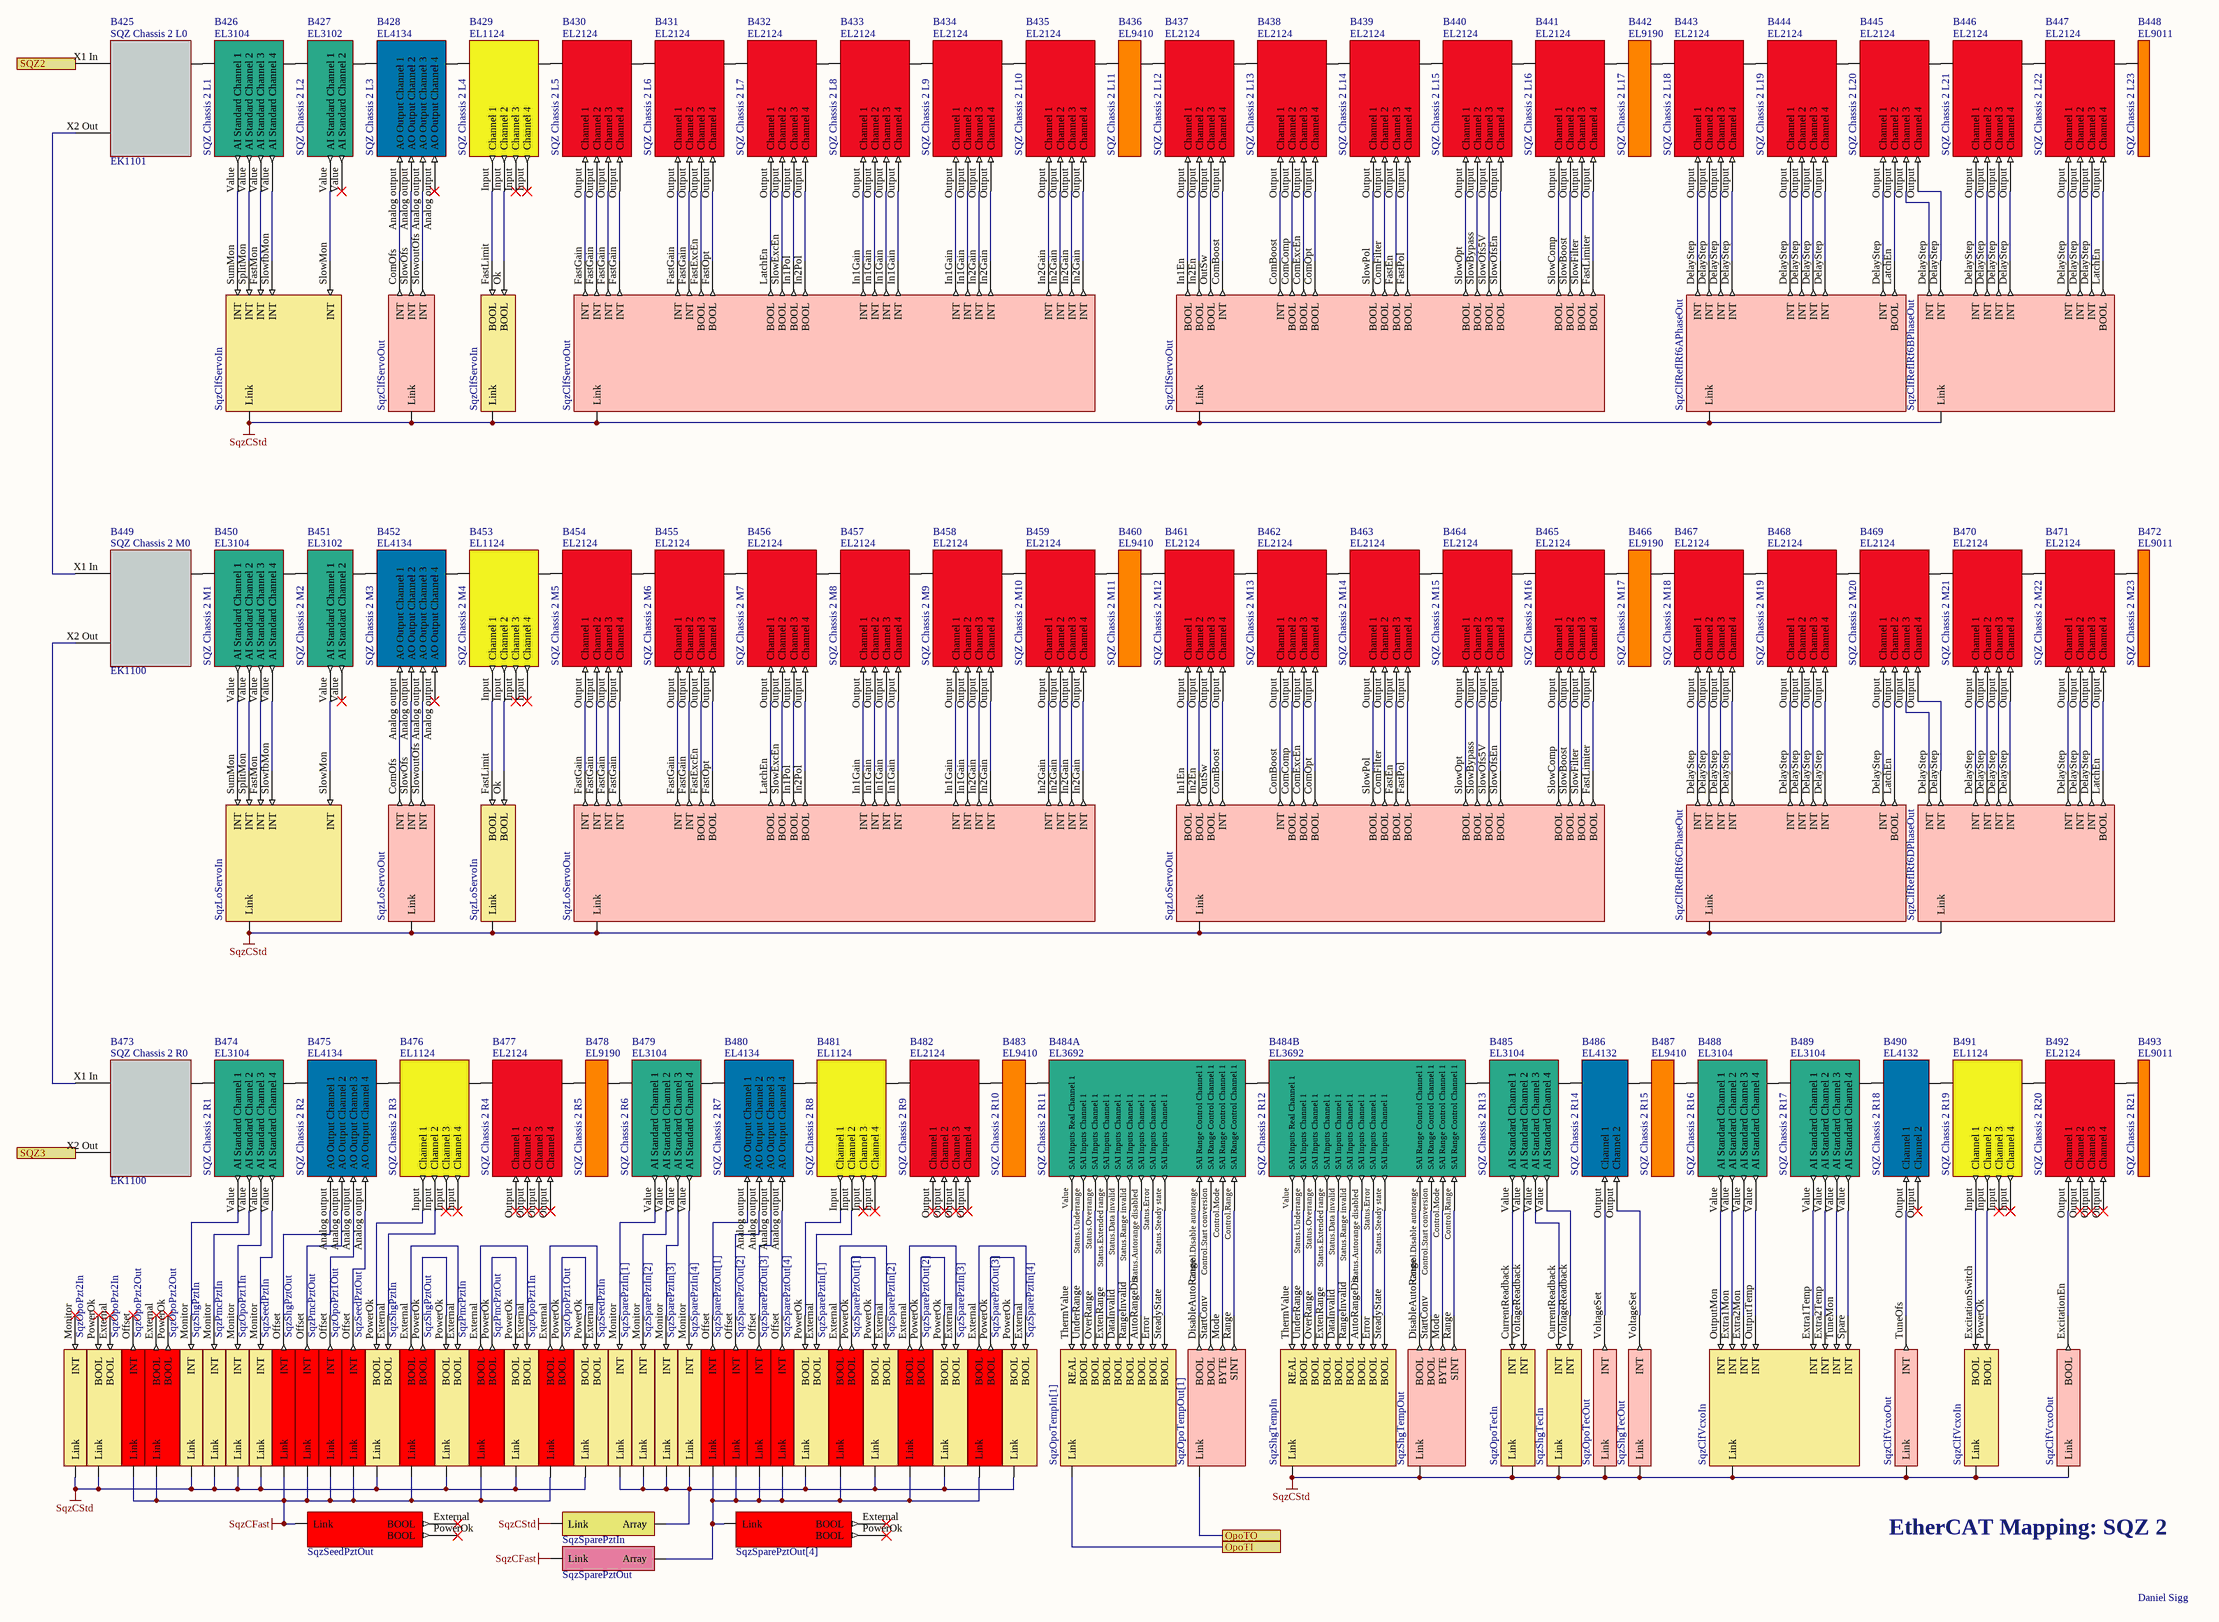
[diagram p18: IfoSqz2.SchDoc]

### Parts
B425  SQZ Chassis 2 L0  Part Number: EK1101
B426  SQZ Chassis 2 L1  Part Number: EL3104  (mechanical)
B427  SQZ Chassis 2 L2  Part Number: EL3102  (mechanical)
B428  SQZ Chassis 2 L3  Part Number: EL4134  (mechanical)
B429  SQZ Chassis 2 L4  Part Number: EL1124  (mechanical)
B430  SQZ Chassis 2 L5  Part Number: EL2124  (mechanical)
B431  SQZ Chassis 2 L6  Part Number: EL2124  (mechanical)
B432  SQZ Chassis 2 L7  Part Number: EL2124  (mechanical)
B433  SQZ Chassis 2 L8  Part Number: EL2124  (mechanical)
B434  SQZ Chassis 2 L9  Part Number: EL2124  (mechanical)
B435  SQZ Chassis 2 L10  Part Number: EL2124  (mechanical)
B436  SQZ Chassis 2 L11  Part Number: EL9410  (mechanical)
B437  SQZ Chassis 2 L12  Part Number: EL2124  (mechanical)
B438  SQZ Chassis 2 L13  Part Number: EL2124  (mechanical)
B439  SQZ Chassis 2 L14  Part Number: EL2124  (mechanical)
B440  SQZ Chassis 2 L15  Part Number: EL2124  (mechanical)
B441  SQZ Chassis 2 L16  Part Number: EL2124  (mechanical)
B442  SQZ Chassis 2 L17  Part Number: EL9190  (mechanical)
B443  SQZ Chassis 2 L18  Part Number: EL2124  (mechanical)
B444  SQZ Chassis 2 L19  Part Number: EL2124  (mechanical)
B445  SQZ Chassis 2 L20  Part Number: EL2124  (mechanical)
B446  SQZ Chassis 2 L21  Part Number: EL2124  (mechanical)
B447  SQZ Chassis 2 L22  Part Number: EL2124  (mechanical)
B448  SQZ Chassis 2 L23  Part Number: EL9011  (mechanical)
B449  SQZ Chassis 2 M0  Part Number: EK1100
B450  SQZ Chassis 2 M1  Part Number: EL3104  (mechanical)
B451  SQZ Chassis 2 M2  Part Number: EL3102  (mechanical)
B452  SQZ Chassis 2 M3  Part Number: EL4134  (mechanical)
B453  SQZ Chassis 2 M4  Part Number: EL1124  (mechanical)
B454  SQZ Chassis 2 M5  Part Number: EL2124  (mechanical)
B455  SQZ Chassis 2 M6  Part Number: EL2124  (mechanical)
B456  SQZ Chassis 2 M7  Part Number: EL2124  (mechanical)
B457  SQZ Chassis 2 M8  Part Number: EL2124  (mechanical)
B458  SQZ Chassis 2 M9  Part Number: EL2124  (mechanical)
B459  SQZ Chassis 2 M10  Part Number: EL2124  (mechanical)
B460  SQZ Chassis 2 M11  Part Number: EL9410  (mechanical)
B461  SQZ Chassis 2 M12  Part Number: EL2124  (mechanical)
B462  SQZ Chassis 2 M13  Part Number: EL2124  (mechanical)
B463  SQZ Chassis 2 M14  Part Number: EL2124  (mechanical)
B464  SQZ Chassis 2 M15  Part Number: EL2124  (mechanical)
B465  SQZ Chassis 2 M16  Part Number: EL2124  (mechanical)
B466  SQZ Chassis 2 M17  Part Number: EL9190  (mechanical)
B467  SQZ Chassis 2 M18  Part Number: EL2124  (mechanical)
B468  SQZ Chassis 2 M19  Part Number: EL2124  (mechanical)
B469  SQZ Chassis 2 M20  Part Number: EL2124  (mechanical)
B470  SQZ Chassis 2 M21  Part Number: EL2124  (mechanical)
B471  SQZ Chassis 2 M22  Part Number: EL2124  (mechanical)
B472  SQZ Chassis 2 M23  Part Number: EL9011  (mechanical)
B473  SQZ Chassis 2 R0  Part Number: EK1100
B474  SQZ Chassis 2 R1  Part Number: EL3104  (mechanical)
B475  SQZ Chassis 2 R2  Part Number: EL4134  (mechanical)
B476  SQZ Chassis 2 R3  Part Number: EL1124  (mechanical)
B477  SQZ Chassis 2 R4  Part Number: EL2124  (mechanical)
B478  SQZ Chassis 2 R5  Part Number: EL9190  (mechanical)
B479  SQZ Chassis 2 R6  Part Number: EL3104  (mechanical)
B480  SQZ Chassis 2 R7  Part Number: EL4134  (mechanical)
B481  SQZ Chassis 2 R8  Part Number: EL1124  (mechanical)
B482  SQZ Chassis 2 R9  Part Number: EL2124  (mechanical)
B483  SQZ Chassis 2 R10  Part Number: EL9410  (mechanical)
B484A  SQZ Chassis 2 R11  Part Number: EL3692  (mechanical)
B484B  SQZ Chassis 2 R12  Part Number: EL3692  (mechanical)
B485  SQZ Chassis 2 R13  Part Number: EL3104  (mechanical)
B486  SQZ Chassis 2 R14  Part Number: EL4132  (mechanical)
B487  SQZ Chassis 2 R15  Part Number: EL9410  (mechanical)
B488  SQZ Chassis 2 R16  Part Number: EL3104  (mechanical)
B489  SQZ Chassis 2 R17  Part Number: EL3104  (mechanical)
B490  SQZ Chassis 2 R18  Part Number: EL4132  (mechanical)
B491  SQZ Chassis 2 R19  Part Number: EL1124  (mechanical)
B492  SQZ Chassis 2 R20  Part Number: EL2124  (mechanical)
B493  SQZ Chassis 2 R21  Part Number: EL9011  (mechanical)
V176  SqzShgTecIn  (no BOM)
V177  SqzShgTecOut  (no BOM)
V289  SqzLoServoIn  (parts A,B of 2)  (no BOM)
V290  SqzLoServoOut  (parts A,B,C of 3)  (no BOM)
V291  SqzClfServoIn  (parts A,B of 2)  (no BOM)
V292  SqzClfServoOut  (parts A,B,C of 3)  (no BOM)
V297  SqzShgTempIn  (no BOM)
V298  SqzShgTempOut  (no BOM)
V303  SqzClfVcxoIn  (parts A,B of 2)  (no BOM)
V304  SqzClfVcxoOut  (parts A,B of 2)  (no BOM)
V305  SqzShgPztIn  (parts A,B of 2)  (no BOM)
V306  SqzPmcPztIn  (parts A,B of 2)  (no BOM)
V307  SqzOpoPzt1In  (parts A,B of 2)  (no BOM)
V308  SqzSeedPztIn  (parts A,B of 2)  (no BOM)
V309  SqzShgPztOut  (parts A,B of 2)  (no BOM)
V310  SqzPmcPztOut  (parts A,B of 2)  (no BOM)
V311  SqzOpoPzt1Out  (parts A,B of 2)  (no BOM)
V312  SqzSeedPztOut  (parts A,B of 2)  (no BOM)
V313  SqzSparePztIn[1]  (parts A,B of 2)  (no BOM)
V314  SqzSparePztIn[2]  (parts A,B of 2)  (no BOM)
V315  SqzSparePztIn[3]  (parts A,B of 2)  (no BOM)
V316  SqzSparePztIn[4]  (parts A,B of 2)  (no BOM)
V317  SqzSparePztOut[1]  (parts A,B of 2)  (no BOM)
V318  SqzSparePztOut[2]  (parts A,B of 2)  (no BOM)
V319  SqzSparePztOut[3]  (parts A,B of 2)  (no BOM)
V320  SqzSparePztOut[4]  (parts A,B of 2)  (no BOM)
V448  SqzClfReflRf6APhaseOut  (no BOM)
V449  SqzClfReflRf6BPhaseOut  (no BOM)
V450  SqzClfReflRf6CPhaseOut  (no BOM)
V452  SqzClfReflRf6DPhaseOut  (no BOM)
V453  SqzOpoTempIn[1]  (no BOM)
V454  SqzOpoTempOut[1]  (no BOM)
V455  SqzOpoTecIn  (no BOM)
V456  SqzOpoTecOut  (no BOM)
V457  SqzSparePztIn  (no BOM)
V458  SqzSparePztOut  (no BOM)
V655  SqzOpoPzt2In  (parts A,B of 2)  (no BOM)
V668  SqzOpoPzt2Out  (parts A,B of 2)  (no BOM)

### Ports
OpoTI, OpoTO, SQZ2, SQZ3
